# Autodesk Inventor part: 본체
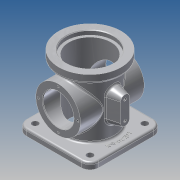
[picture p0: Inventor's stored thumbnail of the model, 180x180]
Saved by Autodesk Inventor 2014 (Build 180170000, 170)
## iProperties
Created: 2021-03
Part Number: 본체
Material: 알루미늄 6061
Document SubType Name: Modeling
Designer: kb542
Density: 2.71 g/cm^3
Appearance: 알루미늄 - 평지
Mass: 834.797 g
Surface Area: 861.783 cm^2
Volume: 308.043 cm^3
Author: kb542
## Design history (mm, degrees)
sketch "스케치1"
  geometry: L1 (0, 0)-(0, -111); L2 (0, 0)-(49, 0); L3 (49, 0)-(49, -13); L4 (49, -13)-(38, -13); L5 (38, -13)-(38, -111); L6 (38, -111)-(0, -111)
  constraints: 12 end point, 3 parallel, 2 perpendicular, 1 vertical
  dimensions: "d0" = 111 distance between parallel lines of L6 L2; "d1" = 76 diameter of L5 L1; "d2" = 98 diameter of L3 L1; "d3" = 13 distance between parallel lines of L4 L2
revolve "회전1" sketch "스케치1" stored, may be unused: angle "d4" = 90 deg
sketch "스케치2"
  geometry: L1 (-57, 57)-(57, 57); L2 (57, 57)-(57, -57); L3 (57, -57)-(-57, -57); L4 (-57, -57)-(-57, 57); C1 r 38 at (0, 0) reference; 2 further points
  constraints: 8 end point, 2 midpoint, 2 parallel, 1 horizontal, 1 horizontal alignment, 1 perpendicular, 1 vertical alignment
  dimensions: "d5" = 114 distance of L1.start L1.end; "d6" = 114 distance of L1.end L2.end
extrude "돌출1" join sketch "스케치2" distance "d7" = 10; taper "d8" = 0 deg
sketch "스케치3"
  geometry: L1 (-49, 0)-(49, 0) reference; L2 (57, -111)-(-57, -111) reference; L3 (0, 0)-(0, -111); L4 (0, 0)-(37, 0); L5 (37, 0)-(37, -7); L6 (37, -7)-(33, -7); L7 (33, -7)-(33, -111); L8 (33, -111)-(0, -111)
  constraints: 12 end point, 2 perpendicular, 2 point on line, 1 collinear, 1 midpoint, 1 parallel
  dimensions: "d9" = 74 diameter of L5 L3; "d10" = 66 diameter of L7 L3; "d11" = 7 distance between parallel lines of L1 L6
revolve "회전2" sketch "스케치3" stored, may be unused: angle "d12" = 90 deg
node "작업 평면1"
sketch "스케치4"
  geometry: L1 (0, 49)-(0, -49) reference; L2 (-111, 57)-(-111, -57) reference; L3 (-13, 38)-(-101, 38) reference; L4 (-13, -38)-(-101, -38) reference; L5 (-57, 38)-(-57, -38); L6 (0, 0)-(-111, 0); C1 r 35 at (-57, 0)
  constraints: 4 end point, 4 midpoint, 1 centre point, 1 perpendicular, 1 point on line
  dimensions: "d14" = 54 distance between parallel lines of L2 L5; "d15" = 70 diameter of C1
extrude "돌출2" join sketch "스케치4" stored distance "d16" = 10; taper "d17" = 0 deg
sketch "스케치5"
  geometry: C1 r 35 at (0, 0) reference; C2 r 24 at (0, 0); 1 further point
  constraints: 1 centre point, 1 coincident
  dimensions: "d18" = 48 diameter of C2
extrude "돌출3" cut sketch "스케치5" stored distance "d19" = 10; taper "d20" = 0 deg
sketch "스케치6" dims "d21" = 62
  geometry: C1 r 24 at (0, 0) reference; C2 r 35 at (0, 0) reference; 6 further points
  constraints: 2 vertical alignment, 1 coincident, 7 other
  dimensions: "d24" = 360 deg dimension on C1.centre point (0, 31) (derived)
hole "구멍1" sketch "스케치6" at (0, 31), (-31, 0), (0, -31), (31, 0) diameter "d26" = 3.242; stored, may be unused: countersink angle "d30" = 90 deg, drill point angle "d32" = 118 deg; dims "d27" = 6, "d28" = 4, "d29" = 2, "d31" = 8
fillet "모깎기1" dims "d33" = 14
sketch "스케치7"
  geometry: A1 r 14 centre (43, 43) between (57, 43) and (43, 57) reference; A2 r 14 centre (-43, 43) between (-43, 57) and (-57, 43) reference; A3 r 14 centre (-43, -43) between (-57, -43) and (-43, -57) reference; A4 r 14 centre (43, -43) between (43, -57) and (57, -43) reference; 4 further points
  constraints: 4 coincident
hole "구멍2" sketch "스케치7" at (-43, 43), (43, 43), (43, -43), (-43, -43) diameter "d34" = 10; stored, may be unused: countersink angle "d38" = 90 deg, drill point angle "d40" = 0 deg; dims "d35" = 6, "d36" = 4, "d37" = 2, "d39" = 8
node "작업 평면3"
sketch "스케치8"
  geometry: L1 (-50, -22)-(-50, -92) reference; L2 (50, -22)-(50, -92) reference; L3 (-50, -57)-(50, -57); L4 (0, -41)-(0, -70); L5 (-7, -41)-(-7, -70); L6 (7, -70)-(7, -41); A1 r 7 centre (0, -41) between (7, -41) and (-7, -41); A2 r 7 centre (0, -70) between (-7, -70) and (7, -70); 3 further points
  constraints: 10 end point, 4 midpoint, 4 point on circle, 4 tangent, 2 centre point, 1 parallel, 1 perpendicular, 1 vertical alignment
  dimensions: "d42" = 43 dimension on A2 A1; "d43" = 14 distance between parallel lines of L5 L6; "d44" = 20 dimension on A2 L3
extrude "돌출4" join sketch "스케치8" stored distance "d45" = 10; taper "d46" = 15 deg
sketch "스케치9"
  geometry: A1 r 7 centre (0, -70) between (-7, -70) and (7, -70) reference; A2 r 7 centre (0, -41) between (7, -41) and (-7, -41) reference; 3 further points
  constraints: 2 coincident
hole "구멍3" sketch "스케치9" at (0, -41), (0, -70) diameter "d47" = 4.134; stored, may be unused: countersink angle "d51" = 90 deg, drill point angle "d53" = 118 deg; dims "d48" = 8, "d49" = 4, "d50" = 2, "d52" = 10
sketch "스케치10"
  geometry: C1 r 38 at (0, 0) reference; C2 r 50 at (0, 0)
  constraints: 1 centre point, 1 coincident, 1 other
  dimensions: "d54" = 100 diameter of C2
feature "엠보싱1" sketch "스케치10" dims "d55" = 1, "d56" = 0
fillet "모깎기2" dims "d57" = 3
chamfer "모따기1" distance "d58" = 1; stored, may be unused: second distance "d59" = 2, angle "d60" = 45 deg
node "솔리드1"
mirror "대칭1"
mirror "대칭2"
node "작업 평면2"
other parameters: "d41" = 55
